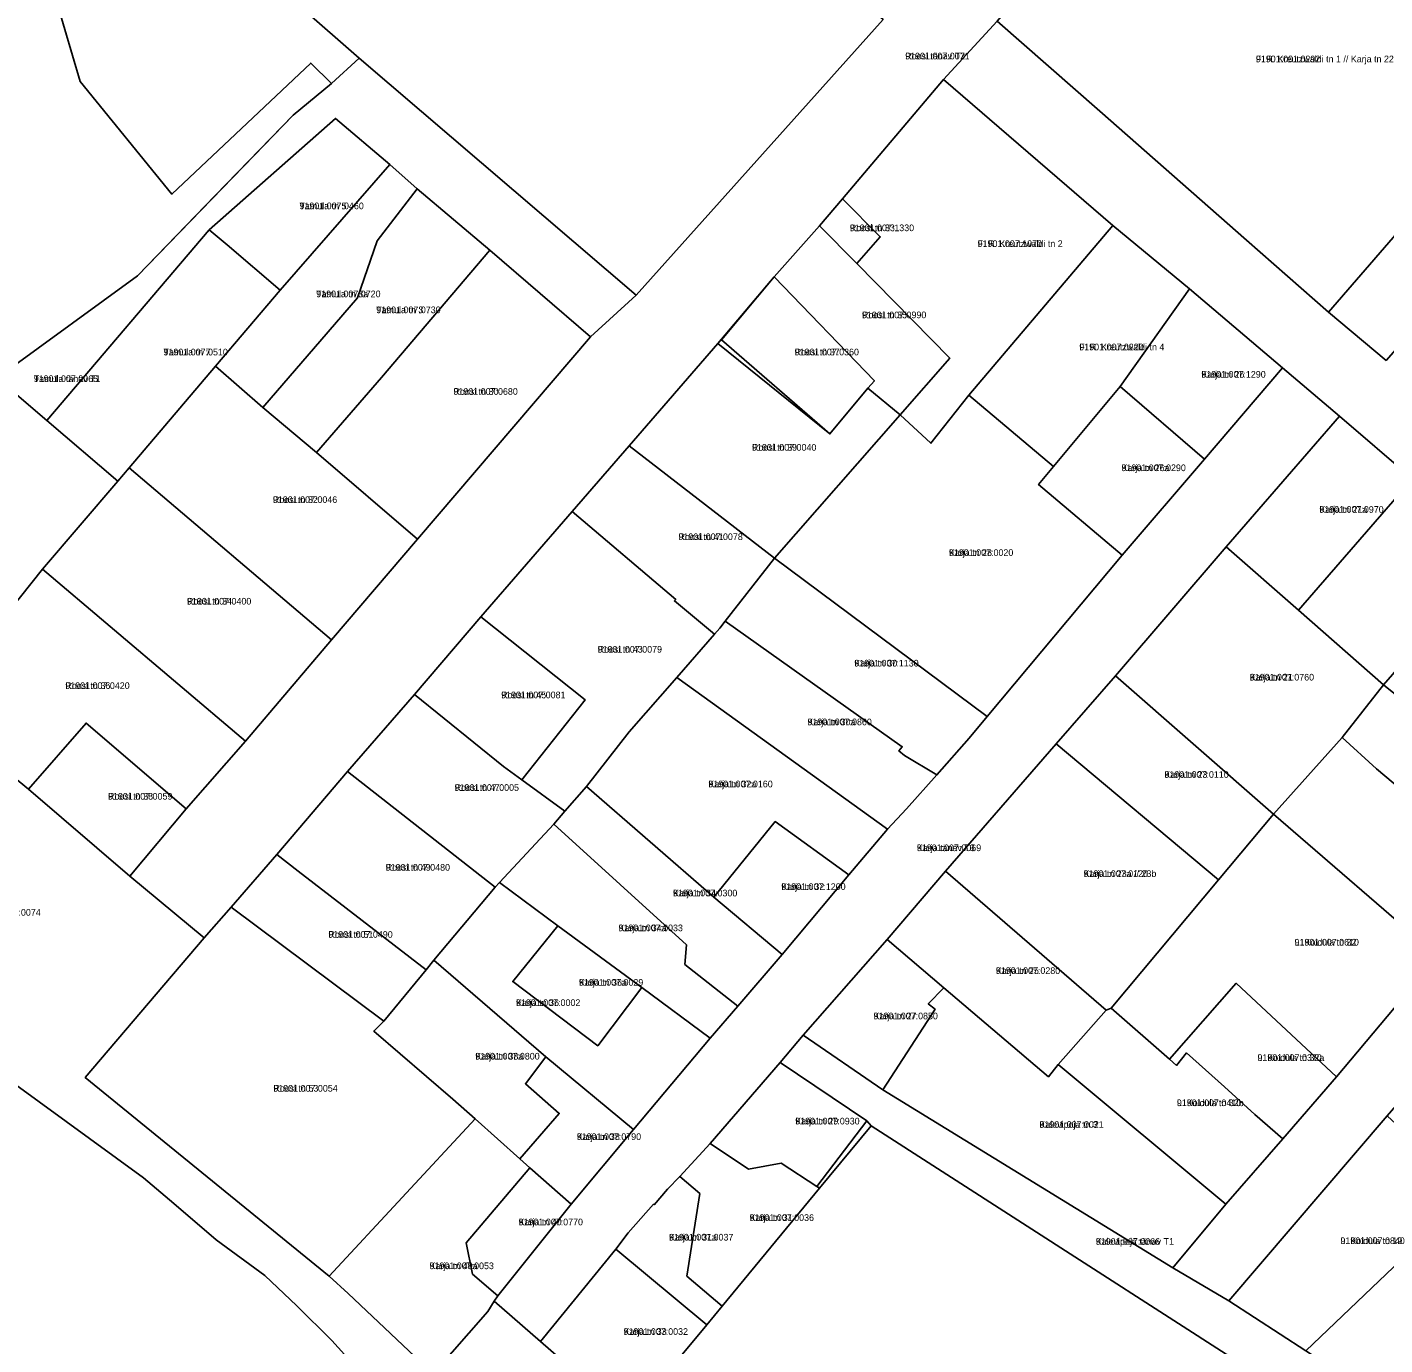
# Model space of a CAD drawing. Extents: x 675810 to 681273, y 6411190 to 6417565.
# Drawn here: x 677202.3 to 677508.4, y 6415481 to 6415777.9 of the extents above; entities that cross this region are included whole.
import ezdxf

# ---------------------------------------------------------------- set-up
doc = ezdxf.new("R2010")
doc.units = 0
for name, color, linetype in [('L_AADRESS', 7, 'Continuous'), ('PIIR', 7, 'Continuous'), ('TUNNUS', 7, 'Continuous')]:
    doc.layers.add(name, color=color, linetype=linetype)

msp = doc.modelspace()

# ---------------------------------------------------------------- linework, layer by layer
at = {"layer": 'PIIR'}
for points in [[(677212.04, 6415827.9), (677269.04, 6415889.58), (677395.25, 6415779.7), (677339.56, 6415717.51), (677277.14, 6415770.95), (677225.12, 6415816.44)], [(677646.67, 6415889.89), (677659.83, 6415878.49), (677628.13, 6415843.17), (677613.21, 6415825.66), (677592.59, 6415800.61), (677575.76, 6415780.87), (677558.51, 6415760.71), (677537.84, 6415736.57), (677523.1, 6415719.23), (677508.64, 6415702.82), (677495.67, 6415713.67), (677523.83, 6415746.25), (677536.7, 6415761.6), (677555.07, 6415782.89), (677568.57, 6415798.61), (677583.48, 6415815.98), (677590, 6415823.63), (677603.42, 6415839.6), (677616.31, 6415854.28)], [(677444.1, 6415758.98), (677420.94, 6415779.32), (677432.33, 6415792.43), (677449.54, 6415811.25), (677463.15, 6415826.36), (677481.9, 6415810.15), (677495.98, 6415797.3), (677514.66, 6415780.78), (677536.7, 6415761.6), (677523.83, 6415746.25), (677495.67, 6415713.67), (677477.14, 6415729.95)], [(677225.12, 6415816.44), (677277.14, 6415770.95), (677270.85, 6415765.21), (677266.19, 6415769.85), (677234.9, 6415740.29), (677214.24, 6415765.69), (677207.34, 6415789.22)], [(677447, 6415733.26), (677414.59, 6415694.98), (677406.01, 6415684.17), (677399.06, 6415690.56), (677410.27, 6415703.33), (677389.35, 6415724.7), (677394.61, 6415730.69), (677386.11, 6415739.24), (677408.85, 6415766.14)], [(677271.82, 6415757.38), (677284.03, 6415747.01), (677259.32, 6415718.65), (677247.38, 6415728.88), (677243.28, 6415732.24)], [(677290.16, 6415741.51), (677281.15, 6415729.8), (677276.72, 6415716.92), (677270.14, 6415709.3), (677255.41, 6415692.19), (677244.73, 6415701.53), (677259.32, 6415718.65), (677284.03, 6415747.01)], [(677290.16, 6415741.51), (677306.55, 6415727.7), (677282.16, 6415699.01), (677267.47, 6415682.09), (677255.41, 6415692.19), (677270.14, 6415709.3), (677276.72, 6415716.92), (677281.15, 6415729.8)], [(677386.11, 6415739.24), (677394.6, 6415730.7), (677389.35, 6415724.7), (677380.87, 6415733.2)], [(677380.87, 6415733.2), (677389.35, 6415724.7), (677410.27, 6415703.33), (677399.06, 6415690.56), (677391.76, 6415696.61), (677393.29, 6415698.21), (677370.68, 6415721.67)], [(677414.59, 6415694.98), (677447, 6415733.26), (677464.35, 6415718.93), (677448.72, 6415696.94), (677433.66, 6415678.9)], [(677243.28, 6415732.24), (677247.38, 6415728.88), (677259.32, 6415718.65), (677244.73, 6415701.53), (677225.26, 6415678.62), (677222.69, 6415675.61), (677206.7, 6415689.28)], [(677329.29, 6415708.13), (677290.24, 6415662.57), (677267.47, 6415682.09), (677282.16, 6415699.01), (677306.55, 6415727.7)], [(677370.68, 6415721.67), (677393.29, 6415698.21), (677391.76, 6415696.61), (677383.23, 6415686.27), (677358.79, 6415707.49)], [(677448.72, 6415696.94), (677464.35, 6415718.93), (677485.26, 6415701.15), (677467.68, 6415680.59)], [(677358.01, 6415706.67), (677383.23, 6415686.27), (677391.76, 6415696.61), (677399.06, 6415690.56), (677370.73, 6415658.28), (677337.98, 6415683.58)], [(677244.73, 6415701.53), (677255.41, 6415692.19), (677267.47, 6415682.09), (677290.24, 6415662.57), (677270.85, 6415639.86), (677225.26, 6415678.62)], [(677485.26, 6415701.15), (677498.11, 6415690.24), (677472.59, 6415660.83), (677447.6, 6415631.75), (677434.27, 6415616.43), (677409.33, 6415587.71), (677396.14, 6415572.29), (677377.21, 6415550.75), (677372.02, 6415544.64), (677356.24, 6415526.32), (677349.39, 6415518.93), (677346.64, 6415516.02), (677343.62, 6415512.54), (677343.47, 6415512.67), (677337.8, 6415506.21), (677334.97, 6415502.53), (677317.98, 6415481.72), (677307.59, 6415490.8), (677308.39, 6415492.05), (677324.92, 6415512.67), (677338.99, 6415529.53), (677356.26, 6415550.05), (677362.46, 6415557.29), (677372.47, 6415568.92), (677387.51, 6415586.87), (677396.24, 6415597.19), (677400.54, 6415601.76), (677407.38, 6415609.42), (677414.64, 6415617.67), (677418.67, 6415622.55), (677449.15, 6415658.91), (677467.68, 6415680.59)], [(677467.68, 6415680.59), (677449.15, 6415658.91), (677430.3, 6415674.84), (677433.66, 6415678.9), (677448.72, 6415696.94)], [(677370.73, 6415658.28), (677399.06, 6415690.56), (677406.01, 6415684.17), (677414.59, 6415694.98), (677433.66, 6415678.9), (677430.3, 6415674.84), (677449.15, 6415658.91), (677418.67, 6415622.55)], [(677472.59, 6415660.83), (677498.11, 6415690.24), (677514.58, 6415676.17), (677488.89, 6415646.54)], [(677337.98, 6415683.58), (677370.73, 6415658.28), (677359.62, 6415644.03), (677358.44, 6415642.51), (677357.23, 6415641.11), (677348.2, 6415648.63), (677348.5, 6415648.97), (677325.12, 6415668.79)], [(677222.69, 6415675.61), (677225.26, 6415678.62), (677270.85, 6415639.86), (677251.48, 6415617), (677205.71, 6415655.76)], [(677533.97, 6415659.49), (677508.07, 6415629.74), (677488.89, 6415646.54), (677514.58, 6415676.17)], [(677325.12, 6415668.79), (677348.5, 6415648.97), (677348.2, 6415648.63), (677357.23, 6415641.11), (677348.71, 6415631.39), (677337.98, 6415619.12), (677328.36, 6415606.8), (677323.52, 6415601.23), (677313.81, 6415608.34), (677328.07, 6415626.36), (677304.55, 6415645.04)], [(677472.59, 6415660.83), (677488.89, 6415646.54), (677508.07, 6415629.74), (677498.73, 6415617.83), (677483.28, 6415600.55), (677447.6, 6415631.75)], [(677533.97, 6415659.49), (677552.93, 6415643.54), (677527.75, 6415613.87), (677508.07, 6415629.74)], [(677414.64, 6415617.67), (677407.38, 6415609.42), (677400.08, 6415613.82), (677398.82, 6415614.84), (677399.54, 6415615.75), (677359.62, 6415644.03), (677370.73, 6415658.28), (677418.67, 6415622.55)], [(677205.71, 6415655.76), (677251.48, 6415617), (677238.1, 6415601.8), (677215.57, 6415621.08), (677202.58, 6415606.2), (677180.56, 6415624.22)], [(677304.55, 6415645.04), (677328.07, 6415626.36), (677313.81, 6415608.34), (677309.63, 6415611.32), (677289.56, 6415627.54)], [(677396.24, 6415597.19), (677348.71, 6415631.39), (677357.23, 6415641.11), (677358.44, 6415642.51), (677359.62, 6415644.03), (677399.54, 6415615.75), (677398.82, 6415614.84), (677400.08, 6415613.82), (677407.38, 6415609.42), (677400.54, 6415601.76)], [(677434.27, 6415616.43), (677447.6, 6415631.75), (677483.28, 6415600.55), (677470.86, 6415585.77)], [(677396.24, 6415597.19), (677387.51, 6415586.87), (677370.93, 6415598.89), (677357.07, 6415581.85), (677328.36, 6415606.8), (677337.98, 6415619.12), (677348.71, 6415631.39)], [(677546.64, 6415598.81), (677535.54, 6415586.39), (677506.49, 6415610.77), (677498.73, 6415617.83), (677508.07, 6415629.74), (677527.75, 6415613.87)], [(677289.56, 6415627.54), (677309.63, 6415611.32), (677313.81, 6415608.34), (677323.52, 6415601.23), (677320.98, 6415598.32), (677308.77, 6415585.14), (677307.79, 6415584.09), (677274.5, 6415610.16)], [(677571.56, 6415627.5), (677583.03, 6415617.83), (677551.18, 6415581.36), (677549.66, 6415579.59), (677532.56, 6415559.91), (677508.91, 6415532.58), (677473.16, 6415490.87), (677460.53, 6415498.36), (677472.49, 6415512.66), (677485.32, 6415527.43), (677497.44, 6415541.36), (677520.31, 6415568.6), (677535.54, 6415586.39), (677546.64, 6415598.81)], [(677215.57, 6415621.08), (677238.1, 6415601.8), (677225.39, 6415586.63), (677202.58, 6415606.2)], [(677483.28, 6415600.55), (677498.73, 6415617.83), (677506.49, 6415610.77), (677535.54, 6415586.39), (677520.31, 6415568.6)], [(677409.33, 6415587.71), (677434.27, 6415616.43), (677470.86, 6415585.77), (677446.64, 6415556.87), (677445.51, 6415556.41)], [(677274.5, 6415610.16), (677307.79, 6415584.09), (677293.98, 6415567.65), (677292.19, 6415565.5), (677263.34, 6415587.71), (677258.55, 6415591.48)], [(677372.47, 6415568.92), (677362.46, 6415557.29), (677350.51, 6415566.7), (677350.93, 6415571.11), (677320.98, 6415598.32), (677323.52, 6415601.23), (677328.36, 6415606.8), (677357.07, 6415581.85)], [(677308.77, 6415585.14), (677320.98, 6415598.32), (677350.93, 6415571.11), (677350.51, 6415566.7), (677362.46, 6415557.29), (677356.26, 6415550.05), (677340.88, 6415561.51), (677321.94, 6415575.44)], [(677372.47, 6415568.92), (677357.07, 6415581.85), (677370.93, 6415598.89), (677387.51, 6415586.87)], [(677459.82, 6415545.34), (677446.64, 6415556.87), (677470.86, 6415585.77), (677483.28, 6415600.55), (677520.31, 6415568.6), (677497.44, 6415541.36), (677474.87, 6415562.46)], [(677258.55, 6415591.48), (677263.34, 6415587.71), (677292.19, 6415565.5), (677282.65, 6415553.95), (677248.28, 6415579.63)], [(677408.96, 6415561.4), (677396.14, 6415572.29), (677409.33, 6415587.71), (677445.51, 6415556.41), (677434.71, 6415544.16), (677432.51, 6415541.41)], [(677308.77, 6415585.14), (677321.94, 6415575.44), (677311.75, 6415562.84), (677330.92, 6415548.36), (677340.88, 6415561.51), (677356.26, 6415550.05), (677338.99, 6415529.53), (677319.2, 6415545.85), (677293.98, 6415567.65), (677307.79, 6415584.09)], [(677248.28, 6415579.63), (677282.65, 6415553.95), (677280.42, 6415551.67), (677298.23, 6415536.36), (677303.25, 6415531.9), (677270.38, 6415496.45), (677215.35, 6415541.25), (677242.19, 6415572.7)], [(677340.88, 6415561.51), (677330.92, 6415548.36), (677311.75, 6415562.84), (677321.94, 6415575.44)], [(677396.14, 6415572.29), (677408.96, 6415561.4), (677405.41, 6415557.83), (677406.94, 6415556.59), (677395.17, 6415538.44), (677377.21, 6415550.75)], [(677292.19, 6415565.5), (677293.98, 6415567.65), (677319.2, 6415545.85), (677314.6, 6415539.8), (677322.24, 6415533.12), (677313.36, 6415522.9), (677303.25, 6415531.9), (677298.23, 6415536.36), (677280.42, 6415551.67), (677282.65, 6415553.95)], [(677408.96, 6415561.4), (677432.51, 6415541.41), (677434.71, 6415544.16), (677472.49, 6415512.66), (677460.53, 6415498.36), (677395.17, 6415538.44), (677406.94, 6415556.59), (677405.41, 6415557.83)], [(677461.38, 6415543.93), (677459.82, 6415545.34), (677474.87, 6415562.46), (677497.44, 6415541.36), (677485.32, 6415527.43), (677479.02, 6415532.89), (677472.22, 6415539.1), (677463.65, 6415546.76)], [(677445.51, 6415556.41), (677446.64, 6415556.87), (677459.82, 6415545.34), (677461.38, 6415543.93), (677463.65, 6415546.76), (677472.22, 6415539.1), (677479.02, 6415532.89), (677485.32, 6415527.43), (677472.49, 6415512.66), (677434.71, 6415544.16)], [(677377.21, 6415550.75), (677395.17, 6415538.44), (677460.53, 6415498.36), (677473.16, 6415490.87), (677490.51, 6415479.64), (677514.44, 6415464.15), (677507.74, 6415456.28), (677392.53, 6415530.33), (677391.54, 6415531.46), (677372.02, 6415544.64)], [(677314.6, 6415539.8), (677319.2, 6415545.85), (677338.99, 6415529.53), (677324.92, 6415512.67), (677315.6, 6415520.9), (677313.36, 6415522.9), (677322.24, 6415533.12)], [(677391.54, 6415531.46), (677380.32, 6415516.64), (677372.27, 6415521.91), (677364.93, 6415520.6), (677356.24, 6415526.32), (677372.02, 6415544.64)], [(677274.63, 6415492.53), (677270.38, 6415496.45), (677303.25, 6415531.9), (677313.36, 6415522.9), (677315.6, 6415520.9), (677301.23, 6415503.97), (677302.65, 6415496.91), (677308.39, 6415492.05), (677307.59, 6415490.8), (677306.11, 6415488.49), (677293.83, 6415474.44)], [(677473.16, 6415490.87), (677508.91, 6415532.58), (677514.96, 6415526.92), (677510.82, 6415522.1), (677523.55, 6415511.07), (677490.51, 6415479.64)], [(677392.53, 6415530.33), (677507.74, 6415456.28), (677527.68, 6415439.36), (677550.13, 6415420.31), (677564.99, 6415407.75), (677582.2, 6415400.99), (677554.69, 6415367.45), (677550.88, 6415368.11), (677485.36, 6415406.68), (677406.64, 6415436.15), (677370.49, 6415446.92), (677334.72, 6415460.59), (677337.9, 6415464.39), (677355.53, 6415485.48), (677358.99, 6415489.69), (677380.91, 6415516.25)], [(677356.24, 6415526.32), (677364.93, 6415520.6), (677372.27, 6415521.91), (677380.32, 6415516.64), (677380.91, 6415516.25), (677358.99, 6415489.69), (677351.02, 6415496.47), (677353.9, 6415515.05), (677349.39, 6415518.93)], [(677302.65, 6415496.91), (677301.23, 6415503.97), (677315.6, 6415520.9), (677324.92, 6415512.67), (677308.39, 6415492.05)], [(677349.39, 6415518.93), (677353.9, 6415515.05), (677351.02, 6415496.47), (677358.99, 6415489.69), (677355.53, 6415485.48), (677334.97, 6415502.53), (677337.8, 6415506.21), (677343.47, 6415512.67), (677343.62, 6415512.54), (677346.64, 6415516.02)], [(677490.51, 6415479.64), (677523.55, 6415511.07), (677541.32, 6415495.69), (677514.44, 6415464.15)], [(677334.97, 6415502.53), (677355.53, 6415485.48), (677337.9, 6415464.39), (677317.98, 6415481.72)]]:
    msp.add_lwpolyline(points, close=True, dxfattribs=at)
for points in [[(677207.34, 6415789.22), (677214.24, 6415765.69), (677234.9, 6415740.29), (677266.19, 6415769.85), (677270.85, 6415765.21), (677262.26, 6415758.1), (677244.69, 6415739.98), (677227.13, 6415721.86), (677196.99, 6415699.93), (677144.99, 6415671.31), (677125.24, 6415664.48), (677102.03, 6415663.02), (677078.82, 6415661.56), (677042.4, 6415655.67), (677021.12, 6415650.85)], [(677420.94, 6415779.32), (677408.85, 6415766.14), (677386.11, 6415739.24), (677380.87, 6415733.2), (677370.68, 6415721.67), (677358.01, 6415706.67), (677337.98, 6415683.58), (677325.12, 6415668.79), (677304.55, 6415645.04), (677289.56, 6415627.54), (677274.5, 6415610.16), (677258.55, 6415591.48), (677248.28, 6415579.63), (677242.19, 6415572.7), (677225.39, 6415586.63), (677238.1, 6415601.8), (677251.48, 6415617), (677270.85, 6415639.86), (677290.24, 6415662.57), (677329.29, 6415708.13), (677339.56, 6415717.51), (677395.25, 6415779.7)], [(677514.58, 6415676.17), (677498.11, 6415690.24), (677485.26, 6415701.15), (677464.35, 6415718.93), (677447, 6415733.26), (677408.85, 6415766.14), (677420.94, 6415779.32), (677444.1, 6415758.98), (677477.14, 6415729.95), (677495.67, 6415713.67), (677508.64, 6415702.82)], [(677196.99, 6415699.93), (677227.13, 6415721.86), (677253.48, 6415749.04), (677262.26, 6415758.1), (677270.85, 6415765.21), (677277.14, 6415770.95), (677339.56, 6415717.51), (677329.29, 6415708.13), (677306.55, 6415727.7), (677290.16, 6415741.51), (677284.03, 6415747.01), (677271.82, 6415757.38), (677243.28, 6415732.24), (677206.7, 6415689.28), (677199.4, 6415695.55)], [(677199.4, 6415695.55), (677206.7, 6415689.28), (677222.69, 6415675.61), (677205.71, 6415655.76), (677180.56, 6415624.22), (677202.58, 6415606.2), (677225.39, 6415586.63), (677242.19, 6415572.7), (677215.35, 6415541.25), (677270.38, 6415496.45), (677274.63, 6415492.53), (677293.83, 6415474.44)], [(677198.9, 6415540.15), (677228.48, 6415518.63), (677235.34, 6415512.81), (677244.88, 6415504.66), (677255.82, 6415496.57), (677263.06, 6415489.8), (677270.93, 6415481.93), (677273.82, 6415478.83)], [(677273.82, 6415478.83), (677270.93, 6415481.93), (677263.06, 6415489.8), (677255.82, 6415496.57), (677244.88, 6415504.66), (677235.34, 6415512.81), (677228.48, 6415518.63), (677198.9, 6415540.15)], [(677293.83, 6415474.44), (677306.11, 6415488.49), (677307.59, 6415490.8), (677317.98, 6415481.72), (677337.9, 6415464.39)]]:
    msp.add_lwpolyline(points, dxfattribs=at)

# ---------------------------------------------------------------- texts
at = {"layer": 'L_AADRESS'}
for s, p in [('Roosi tänav T2', (677400.23, 6415770.67)), ('F. R. Kreutzwaldi tn 1 // Karja tn 22 // 24 // Roosi tn 29', (677479.28, 6415770.02)), ('Tamula tn 5', (677263.66, 6415736.91)), ('Roosi tn 33', (677387.73, 6415731.96)), ('F. R. Kreutzwaldi tn 2', (677416.55, 6415728.4)), ('Tamula tn 3a', (677267.44, 6415717.07)), ('Tamula tn 3', (677280.98, 6415713.48)), ('Roosi tn 35', (677390.48, 6415712.34)), ('Tamula tn 7', (677233.01, 6415703.96)), ('Roosi tn 37', (677375.29, 6415703.97)), ('F. R. Kreutzwaldi tn 4', (677439.47, 6415705.11)), ('Tamula tänav T1', (677203.76, 6415697.96)), ('Karja tn 26', (677466.99, 6415698.94)), ('Roosi tn 30', (677298.38, 6415695.08)), ('Roosi tn 39', (677365.69, 6415682.48)), ('Karja tn 26a', (677448.99, 6415677.88)), ('Roosi tn 32', (677257.67, 6415670.7)), ('Karja tn 21a', (677493.59, 6415668.49)), ('Roosi tn 41', (677349.1, 6415662.34)), ('Karja tn 28', (677410.09, 6415658.77)), ('Roosi tn 34', (677238.3, 6415647.81)), ('Roosi tn 43', (677330.89, 6415636.97)), ('Karja tn 30', (677388.75, 6415633.85)), ('Karja tn 21', (677477.9, 6415630.69)), ('Roosi tn 36', (677210.88, 6415628.78)), ('Roosi tn 45', (677309.13, 6415626.69)), ('Karja tn 30a', (677378.19, 6415620.61)), ('Karja tn 23', (677458.66, 6415608.76)), ('Roosi tn 47', (677298.65, 6415605.82)), ('Karja tn 32a', (677355.85, 6415606.62)), ('Roosi tn 38', (677220.51, 6415603.85)), ('Karja tänav T3', (677402.85, 6415592.24)), ('Roosi tn 49', (677283.1, 6415587.83)), ('Karja tn 23a // 23b', (677440.45, 6415586.42)), ('Karja tn 34', (677347.87, 6415582.04)), ('Karja tn 32', (677372.29, 6415583.49)), ('Roosi tn 51', (677270.18, 6415572.71)), ('Karja tn 34a', (677335.6, 6415574.19)), ('L. Koidula tn 32', (677488.01, 6415570.96)), ('Karja tn 25', (677420.66, 6415564.56)), ('Karja tn 36a', (677326.67, 6415561.9)), ('Karja tn 36', (677312.48, 6415557.34)), ('Karja tn 27', (677393.09, 6415554.34)), ('Karja tn 38a', (677303.31, 6415545.27)), ('L. Koidula tn 32a', (677479.64, 6415544.95)), ('Roosi tn 53', (677257.78, 6415538.04)), ('L. Koidula tn 32b', (677461.47, 6415534.77)), ('Karja tn 29', (677375.44, 6415530.64)), ('Kalevipoja tn 3', (677430.48, 6415529.88)), ('Karja tn 38', (677326.18, 6415527.14)), ('Karja tn 40', (677313.07, 6415507.91)), ('Karja tn 31', (677365.15, 6415508.9)), ('Karja tn 31a', (677346.98, 6415504.48)), ('Kalevipoja tänav T1', (677443.19, 6415503.52)), ('L. Koidula tn 19', (677498.35, 6415503.68)), ('Karja tn 40a', (677292.99, 6415498.03)), ('Karja tn 33', (677336.75, 6415483.22))]:
    msp.add_text(s, height=1.5, dxfattribs=at).set_placement(p)
at = {"layer": 'TUNNUS'}
for s, p in [('91901:007:0071', (677400.23, 6415770.67)), ('91901:001:0292', (677479.28, 6415770.02)), ('91901:007:0460', (677263.66, 6415736.91)), ('91901:007:1330', (677387.73, 6415731.96)), ('91901:007:1070', (677416.55, 6415728.4)), ('91901:007:0720', (677267.44, 6415717.07)), ('91901:007:0730', (677280.98, 6415713.48)), ('91901:007:0990', (677390.48, 6415712.34)), ('91901:007:0510', (677233.01, 6415703.96)), ('91901:007:0360', (677375.29, 6415703.97)), ('91901:007:0220', (677439.47, 6415705.11)), ('91901:007:0065', (677203.76, 6415697.96)), ('91901:007:1290', (677466.99, 6415698.94)), ('91901:007:0680', (677298.38, 6415695.08)), ('91901:007:0040', (677365.69, 6415682.48)), ('91901:007:0290', (677448.99, 6415677.88)), ('91901:007:0046', (677257.67, 6415670.7)), ('91901:007:0970', (677493.59, 6415668.49)), ('91901:007:0078', (677349.1, 6415662.34)), ('91901:007:0020', (677410.09, 6415658.77)), ('91901:007:0400', (677238.3, 6415647.81)), ('91901:007:0079', (677330.89, 6415636.97)), ('91901:007:1130', (677388.75, 6415633.85)), ('91901:007:0760', (677477.9, 6415630.69)), ('91901:007:0420', (677210.88, 6415628.78)), ('91901:007:0081', (677309.13, 6415626.69)), ('91901:007:0860', (677378.19, 6415620.61)), ('91901:007:0005', (677298.65, 6415605.82)), ('91901:007:0160', (677355.85, 6415606.62)), ('91901:007:0110', (677458.66, 6415608.76)), ('91901:007:0059', (677220.51, 6415603.85)), ('91901:007:0069', (677402.85, 6415592.24)), ('91901:007:0480', (677283.1, 6415587.83)), ('91901:007:0120', (677440.45, 6415586.42)), ('91901:007:0300', (677347.87, 6415582.04)), ('91901:007:1200', (677372.29, 6415583.49)), ('91901:007:0074', (677190.83, 6415577.68)), ('91901:007:0490', (677270.18, 6415572.71)), ('91901:007:0033', (677335.6, 6415574.19)), ('91901:007:0610', (677488.01, 6415570.96)), ('91901:007:0280', (677420.66, 6415564.56)), ('91901:007:0029', (677326.67, 6415561.9)), ('91901:007:0002', (677312.48, 6415557.34)), ('91901:007:0850', (677393.09, 6415554.34)), ('91901:007:0800', (677303.31, 6415545.27)), ('91901:007:0370', (677479.64, 6415544.95)), ('91901:007:0054', (677257.78, 6415538.04)), ('91901:007:0410', (677461.47, 6415534.77)), ('91901:007:0930', (677375.44, 6415530.64)), ('91901:007:0021', (677430.48, 6415529.88)), ('91901:007:0790', (677326.18, 6415527.14)), ('91901:007:0770', (677313.07, 6415507.91)), ('91901:007:0036', (677365.15, 6415508.9)), ('91901:007:0037', (677346.98, 6415504.48)), ('91901:007:0066', (677443.19, 6415503.52)), ('91901:007:0840', (677498.35, 6415503.68)), ('91901:007:0053', (677292.99, 6415498.03)), ('91901:007:0032', (677336.75, 6415483.22))]:
    msp.add_text(s, height=1.5, dxfattribs=at).set_placement(p)

doc.saveas('drawing.dxf')
